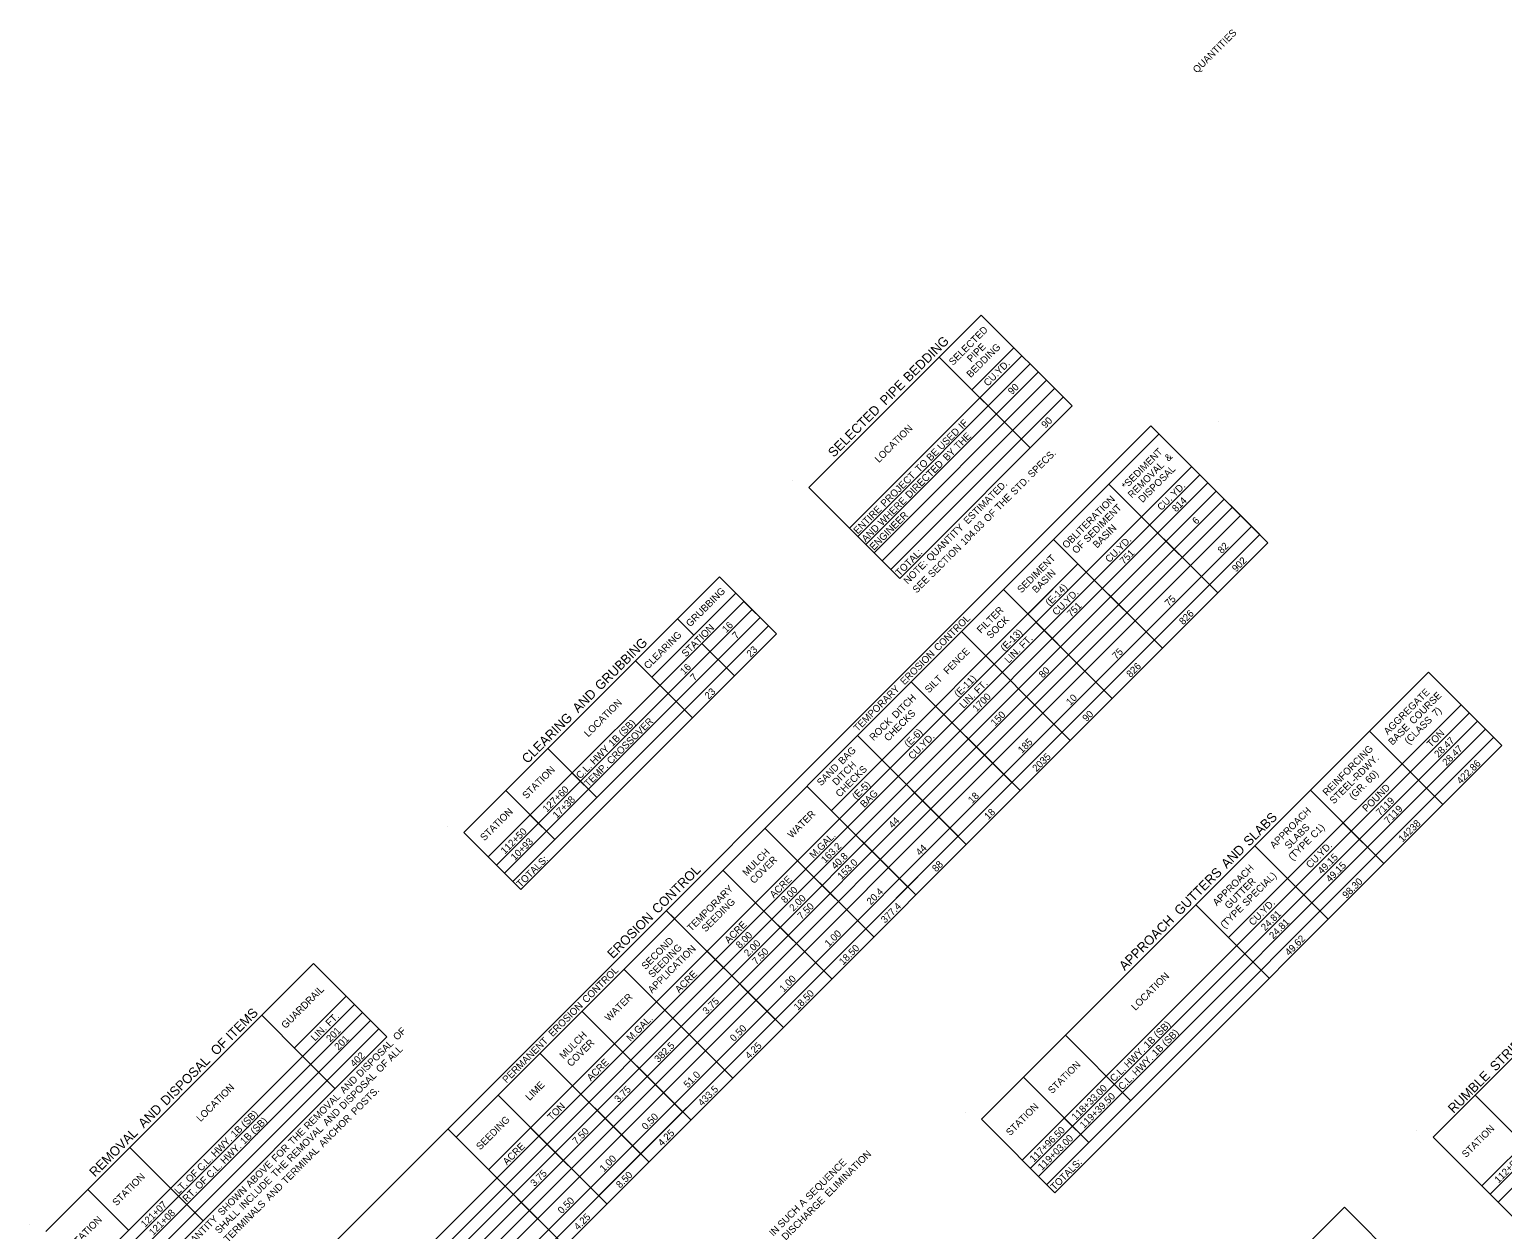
# Model space of a CAD drawing. Extents: x 1675667 to 1681231, y 227227 to 232694.
# Drawn here: x 1676937 to 1678183, y 229090 to 230105 of the extents above; entities that cross this region are included whole.
import ezdxf

# ---------------------------------------------------------------- set-up
doc = ezdxf.new("R2010")
doc.units = 0
for name, color, linetype in [('Default', 7, 'Continuous'), ('R_Annotation', 7, 'Continuous'), ('R_Border', 7, 'Continuous')]:
    doc.layers.add(name, color=color, linetype=linetype)

msp = doc.modelspace()

# ---------------------------------------------------------------- linework, layer by layer
at = {"layer": 'Default'}
for p, q in [((1677596.4, 229717.2), (1677742.2, 229863)), ((1677819.1, 229786.1), (1677742.2, 229863)), ((1677819.1, 229786.1), (1677742.2, 229863)), ((1677734.3, 229799.9), (1677769.8, 229835.4)), ((1677630.9, 229682.7), (1677776.7, 229828.5)), ((1677783.6, 229750.6), (1677706.7, 229827.5)), ((1677637.8, 229675.8), (1677783.6, 229821.7)), ((1677644.7, 229668.9), (1677790.5, 229814.8)), ((1677651.6, 229662), (1677797.4, 229807.9)), ((1677658.5, 229655.1), (1677804.3, 229801)), ((1677665.7, 229647.9), (1677811.5, 229793.7)), ((1677673.3, 229640.3), (1677819.1, 229786.1)), ((1677783.6, 229750.6), (1677741.2, 229793)), ((1677056.4, 228939.9), (1677885.7, 229769.4)), ((1677298.1, 229167.8), (1677892.6, 229762.5)), ((1677984.7, 229670.5), (1677885.7, 229769.4)), ((1677325.6, 229140.2), (1677920.2, 229734.9)), ((1677830.9, 229645.6), (1677920.2, 229734.9)), ((1677097.8, 228898.5), (1677927.1, 229728)), ((1677582.7, 229722.7), (1677582.7, 229722.7)), ((1677977.8, 229677.4), (1677927.1, 229728)), ((1677104.7, 228891.6), (1677934, 229721.1)), ((1677111.6, 228884.7), (1677940.9, 229714.2)), ((1677673.3, 229640.3), (1677596.4, 229717.2)), ((1677673.3, 229640.3), (1677596.4, 229717.2)), ((1677942.3, 229628.1), (1677850.2, 229720.1)), ((1677118.5, 228877.9), (1677947.8, 229707.3)), ((1677125.4, 228871), (1677954.7, 229700.4)), ((1677132.3, 228864.1), (1677961.6, 229693.6)), ((1677942.3, 229628.1), (1677877.8, 229692.5)), ((1677141.6, 228854.8), (1677970.9, 229684.2)), ((1677148.5, 228847.9), (1677977.8, 229677.4)), ((1677895.4, 229581.2), (1677803.3, 229673.2)), ((1677935.4, 229634.9), (1677977.8, 229677.4)), ((1677155.4, 228841), (1677984.7, 229670.5)), ((1677615.5, 229443.9), (1677824, 229652.5)), ((1677781.6, 229610.1), (1677824, 229652.5)), ((1677304.7, 229425.4), (1677520.8, 229641.5)), ((1677569.1, 229593.3), (1677520.8, 229641.5)), ((1677534.6, 229627.7), (1677520.8, 229641.5)), ((1677895.4, 229581.2), (1677830.9, 229645.6)), ((1677463.6, 229556.7), (1677534.6, 229627.7)), ((1677853, 229538.8), (1677761, 229630.8)), ((1677768.2, 229467.7), (1677935.4, 229634.9)), ((1677325.4, 229404.7), (1677541.5, 229620.8)), ((1677332.3, 229397.8), (1677548.4, 229614)), ((1677562.2, 229600.2), (1677541.5, 229620.8)), ((1677339.2, 229390.9), (1677555.3, 229607.1)), ((1677346.1, 229384), (1677562.2, 229600.2)), ((1677417.1, 229455), (1677562.2, 229600.2)), ((1677499.1, 229592.2), (1677485.3, 229606)), ((1677853, 229538.8), (1677788.5, 229603.2)), ((1677353, 229377.1), (1677569.1, 229593.3)), ((1677533.6, 229557.8), (1677506, 229585.3)), ((1677533.6, 229557.8), (1677506, 229585.3)), ((1677817.5, 229503.3), (1677725.5, 229595.3)), ((1677817.5, 229503.3), (1677725.5, 229595.3)), ((1677498.1, 229522.3), (1677449.8, 229570.5)), ((1677742.4, 229182.9), (1678120.5, 229561.1)), ((1678182.6, 229499), (1678120.5, 229561.1)), ((1677491.2, 229529.1), (1677463.6, 229556.7)), ((1677775.1, 229460.8), (1677683.1, 229552.9)), ((1677768.2, 229467.7), (1677710.6, 229525.3)), ((1677776.9, 229148.4), (1678155, 229526.6)), ((1677951.3, 229336.6), (1678148.1, 229533.5)), ((1678182.6, 229499), (1678148.1, 229533.5)), ((1677783.8, 229141.5), (1678161.9, 229519.7)), ((1677790.7, 229134.6), (1678168.8, 229512.8)), ((1678132.6, 229449), (1678070.5, 229511.1)), ((1677729.6, 229415.3), (1677637.6, 229507.4)), ((1677797.6, 229127.7), (1678175.7, 229505.9)), ((1677804.5, 229120.8), (1678182.6, 229499)), ((1677417.1, 229455), (1677375.7, 229496.4)), ((1677417.1, 229455), (1677396.4, 229475.7)), ((1677722.7, 229422.2), (1677665.1, 229479.8)), ((1678132.6, 229449), (1678098.1, 229483.5)), ((1677381.6, 229419.5), (1677340.2, 229460.9)), ((1677686.9, 229372.6), (1677594.8, 229464.6)), ((1677609, 229308.5), (1677768.2, 229467.7)), ((1678082.6, 229399.1), (1678020.6, 229461.1)), ((1677381.6, 229419.5), (1677360.9, 229440.2)), ((1677680, 229379.5), (1677622.4, 229437)), ((1677290.9, 229430.9), (1677290.9, 229430.9)), ((1677353, 229377.1), (1677304.7, 229425.4)), ((1677353, 229377.1), (1677304.7, 229425.4)), ((1677651.4, 229337.1), (1677559.3, 229429.1)), ((1678082.6, 229399.1), (1678048.1, 229433.5)), ((1678035.7, 229352.2), (1677973.7, 229414.2)), ((1677651.4, 229337.1), (1677586.9, 229401.5)), ((1677615.9, 229301.6), (1677523.8, 229393.6)), ((1678035.7, 229352.2), (1678001.3, 229386.6)), ((1677615.9, 229301.6), (1677551.4, 229366)), ((1677985.8, 229302.2), (1677923.7, 229364.2)), ((1678124.4, 229167.8), (1678325.3, 229368.8)), ((1677482.8, 229352.6), (1677475.9, 229359.5)), ((1677574.9, 229260.5), (1677475.9, 229359.5)), ((1677568, 229267.4), (1677510.4, 229325)), ((1677985.8, 229302.2), (1677958.2, 229329.8)), ((1678165.7, 229126.5), (1678366.7, 229327.5)), ((1676951.2, 229088.1), (1677177.6, 229314.6)), ((1677212.1, 229280.1), (1677177.6, 229314.6)), ((1677239.7, 229252.5), (1677177.6, 229314.6)), ((1678172.6, 229119.6), (1678373.6, 229320.6)), ((1678179.5, 229112.7), (1678380.5, 229313.7)), ((1677532.1, 229217.8), (1677440.1, 229309.8)), ((1677568, 229267.4), (1677609, 229308.5)), ((1677161.4, 229243.2), (1677205.2, 229287)), ((1676985.6, 229053.6), (1677212.1, 229280.1)), ((1676985.6, 229053.6), (1677212.1, 229280.1)), ((1677239.7, 229252.5), (1677212.1, 229280.1)), ((1677496.6, 229182.3), (1677404.6, 229274.3)), ((1677525.2, 229224.7), (1677467.6, 229282.2)), ((1676992.5, 229046.7), (1677219, 229273.2)), ((1676999.4, 229039.8), (1677225.9, 229266.3)), ((1677168.3, 229236.3), (1677133.8, 229270.8)), ((1677418.7, 229118.2), (1677568, 229267.4)), ((1677006.3, 229032.9), (1677232.8, 229259.4)), ((1677013.2, 229026), (1677239.7, 229252.5)), ((1677868.6, 229198.7), (1677813.4, 229253.9)), ((1677461.1, 229146.8), (1677369.1, 229238.8)), ((1677489.7, 229189.2), (1677432.1, 229246.7)), ((1677195.9, 229208.7), (1677168.3, 229236.3)), ((1677833.1, 229163.2), (1677777.9, 229218.4)), ((1677868.6, 229198.7), (1677847.9, 229219.4)), ((1677425.6, 229111.3), (1677333.6, 229203.3)), ((1677454.2, 229153.7), (1677396.6, 229211.2)), ((1678228.8, 229134.4), (1678159.9, 229203.3)), ((1678228.8, 229134.4), (1678159.9, 229203.3)), ((1677728.6, 229188.4), (1677728.6, 229188.4)), ((1677390.1, 229075.8), (1677291.2, 229174.7)), ((1677425.6, 229111.3), (1677361.1, 229175.7)), ((1677804.5, 229120.8), (1677742.4, 229182.9)), ((1677804.5, 229120.8), (1677742.4, 229182.9)), ((1677833.1, 229163.2), (1677812.4, 229183.9)), ((1678110.6, 229173.3), (1678110.6, 229173.3)), ((1678200.2, 229092), (1678124.4, 229167.8)), ((1678200.2, 229092), (1678124.4, 229167.8)), ((1677056.6, 229124.6), (1677022.2, 229159.1)), ((1677084.2, 229097), (1677056.6, 229124.6)), ((1677367, 229098.8), (1677332.5, 229133.3)), ((1677021.1, 229089.1), (1676986.7, 229123.6)), ((1677481.3, 228540.5), (1678049.3, 229108.6)), ((1678160, 228998), (1678049.3, 229108.6)), ((1676937.4, 229093.6), (1676937.4, 229093.6))]:
    msp.add_line(p, q, dxfattribs=at)
at = {"layer": 'R_Annotation'}
msp.add_line((1677942.7, 229772.9), (1677942.7, 229772.9), dxfattribs=at)

# ---------------------------------------------------------------- texts
at = {"layer": 'Default'}
for s, height, p in [('SELECTED', 6, (1677718.4, 229820)), (' BEDDING', 8, (1677679.1, 229803.8)), ('BEDDING', 6, (1677733.3, 229809.5)), ('PIPE', 6, (1677733.8, 229822.7)), ('CU.YD.', 6, (1677747.8, 229802.3)), (' PIPE', 8, (1677659.2, 229784)), ('90', 6, (1677768.3, 229795.2)), ('SELECTED', 8, (1677617.5, 229742.2)), (' IF', 6, (1677724.9, 229764.6)), ('90', 6, (1677796.6, 229766.9)), ('LOCATION', 6, (1677655.7, 229737.7)), (' USED', 6, (1677707.1, 229746.8)), (' THE', 6, (1677721.3, 229747.2)), (' BE', 6, (1677697.9, 229737.6)), (' BY', 6, (1677711.8, 229737.7)), (' SPECS.', 6, (1677783.6, 229723.4)), ('*SEDIMENT', 6, (1677864.6, 229715.3)), (' DIRECTED', 6, (1677680.1, 229706.1)), (' TO', 6, (1677688.3, 229728)), ('REMOVAL', 6, (1677869.7, 229707.7)), (' &', 6, (1677899.1, 229737.2)), (' PROJECT', 6, (1677659.1, 229698.8)), (' STD.', 6, (1677769, 229708.7)), ('DISPOSAL', 6, (1677878.6, 229703.9)), (' ESTIMATED.', 6, (1677729.2, 229684.1)), (' THE', 6, (1677755.8, 229695.6)), ('OBLITERATION', 6, (1677814.3, 229665.1)), (' YD.', 6, (1677904.4, 229707)), ('ENTIRE', 6, (1677637.7, 229677.4)), (' WHERE', 6, (1677656.8, 229682.7)), (' OF', 6, (1677746.2, 229685.9)), (' SEDIMENT', 6, (1677830.6, 229668.6)), ('CU.', 6, (1677894.6, 229697.2)), ('814', 6, (1677907.1, 229696)), ('AND', 6, (1677644.6, 229670.5)), ('ENGINEER', 6, (1677651.4, 229663.6)), (' QUANTITY', 6, (1677697.7, 229652.6)), (' 104.03', 6, (1677726.7, 229666.4)), ('BASIN', 6, (1677840.1, 229665.4)), ('6', 6, (1677924.2, 229685.5)), ('OF', 6, (1677822.6, 229660.7)), ('CU.YD.', 6, (1677850.6, 229653.2)), ('TOTAL:', 6, (1677673.2, 229641.9)), (' SECTION', 6, (1677699.2, 229638.9)), ('SEDIMENT', 6, (1677776.2, 229627.5)), ('751', 6, (1677862.9, 229651.7)), ('82', 6, (1677945.7, 229660.8)), ('NOTE:', 6, (1677680.1, 229635)), ('BASIN', 6, (1677788.8, 229627.4)), ('902', 6, (1677957.8, 229645.3)), ('SEE', 6, (1677687.6, 229627.4)), ('(E-14)', 6, (1677800, 229616.4)), ('GRUBBING', 6, (1677496.1, 229598.8)), ('CU.YD.', 6, (1677805.9, 229608.5)), ('75', 6, (1677901, 229616.1)), ('FILTER', 6, (1677742.1, 229593.4)), ('751', 6, (1677818.3, 229607.1)), ('826', 6, (1677913.1, 229600.6)), ('STATION', 6, (1677492.4, 229573.4)), ('16', 6, (1677526.6, 229593.9)), (' CONTROL', 6, (1677704.2, 229576.7)), ('SOCK', 6, (1677750.3, 229588.8)), (' GRUBBING', 8, (1677418.2, 229542.9)), ('CLEARING', 6, (1677460.5, 229563.1)), ('7', 6, (1677535.2, 229588.6)), ('(E-13)', 6, (1677761.9, 229578.2)), (' FT.', 6, (1677776.3, 229578.9)), ('23', 6, (1677547.3, 229573.2)), (' EROSION', 6, (1677675.7, 229548.2)), ('  FENCE', 6, (1677710.7, 229555.6)), ('LIN.', 6, (1677765.5, 229568.1)), ('75', 6, (1677856.4, 229571.4)), ('16', 6, (1677491.1, 229558.4)), ('80', 6, (1677794.4, 229555.6)), ('826', 6, (1677868.5, 229556)), ('7', 6, (1677499.7, 229553.1)), ('TEMPORARY', 6, (1677637.8, 229510.3)), ('SILT', 6, (1677698, 229542.9)), ('(E-11)', 6, (1677722.9, 229539.3)), (' FT.', 6, (1677738.2, 229540.8)), (' AND', 8, (1677399.3, 229524)), ('LOCATION', 6, (1677410, 229505.7)), ('23', 6, (1677511.8, 229537.7)), (' DITCH', 6, (1677668.7, 229519.9)), ('LIN.', 6, (1677727.4, 229530)), ('1700', 6, (1677738.3, 229527.1)), ('10', 6, (1677817.5, 229532.5)), ('AGGREGATE', 6, (1678086.1, 229507.6)), (' COURSE', 6, (1678106.2, 229514.9)), ('CLEARING', 8, (1677358.5, 229483.2)), ('CHECKS', 6, (1677663.6, 229502.1)), ('150', 6, (1677753.8, 229515)), ('90', 6, (1677831.3, 229518.7)), ('(CLASS', 6, (1678103.6, 229499.6)), (' 7)', 6, (1678125.4, 229521.4)), (' CROSSOVER', 6, (1677427.6, 229481.1)), (' (SB)', 6, (1677437.5, 229504.7)), ('ROCK', 6, (1677651.2, 229502.5)), ('(E-6)', 6, (1677680.6, 229497)), ('BASE', 6, (1678090, 229498.7)), ('TON', 6, (1678122.6, 229496.9)), (' HWY', 6, (1677413.5, 229480.7)), (' 1B', 6, (1677428.9, 229496.1)), ('CU.YD.', 6, (1677684.1, 229486.7)), ('185', 6, (1677776.8, 229491.9)), ('REINFORCING', 6, (1678034.5, 229456)), ('28.47', 6, (1678128.8, 229488.3)), ('28.47', 6, (1678135.7, 229481.4)), ('DITCH', 6, (1677619.8, 229464.7)), (' BAG', 6, (1677623.3, 229480.9)), ('2035', 6, (1677789, 229476.4)), ('STEEL-RDWY.', 6, (1678040.4, 229449.1)), ('422.86', 6, (1678147.8, 229465.9)), ('STATION', 6, (1677357.7, 229453.4)), ('C.L.', 6, (1677403.1, 229470.3)), ('TEMP.', 6, (1677410, 229463.5)), ('SAND', 6, (1677606.8, 229464.4)), ('CHECKS', 6, (1677622.6, 229454.8)), (' 60)', 6, (1678068.9, 229464.9)), ('127+60', 6, (1677374.9, 229442.1)), ('(E-5)', 6, (1677636.5, 229452.8)), ('BAG', 6, (1677643.4, 229446)), ('(GR.', 6, (1678056.8, 229452.8)), ('POUND', 6, (1678068.1, 229442.4)), ('17+38', 6, (1677383.4, 229436.8)), ('18', 6, (1677734.6, 229449.6)), ('7119', 6, (1678079.6, 229439.1)), ('7119', 6, (1678086.5, 229432.2)), ('STATION', 6, (1677322.1, 229417.9)), ('WATER', 6, (1677582.1, 229420.1)), ('44', 6, (1677667.4, 229428.5)), ('18', 6, (1677748.3, 229435.8)), (' SLABS', 8, (1677966.7, 229411.2)), ('APPROACH', 6, (1677989.9, 229411.4)), ('14238', 6, (1678098.6, 229416.8)), ('112+50', 6, (1677339.4, 229406.6)), ('SLABS', 6, (1678002.3, 229411)), (' C1)', 6, (1678022.5, 229418.5)), ('10+93', 6, (1677347.9, 229401.3)), ('MULCH', 6, (1677543.8, 229388.1)), ('M.GAL.', 6, (1677600.5, 229403.1)), ('163.2', 6, (1677610.3, 229399.1)), ('44', 6, (1677690.4, 229405.4)), (' AND', 8, (1677947.8, 229392.3)), ('(TYPE', 6, (1678005.4, 229401.4)), ('CU.YD.', 6, (1678020.4, 229394.7)), ('TOTALS:', 6, (1677352.8, 229378.6)), ('COVER', 6, (1677550.1, 229381.7)), ('40.8', 6, (1677618.9, 229393.8)), ('153.0', 6, (1677624.1, 229385.3)), ('88', 6, (1677704.2, 229391.6)), ('APPROACH', 6, (1677941.5, 229362.9)), ('49.15', 6, (1678030.3, 229389.8)), ('49.15', 6, (1678037.2, 229382.9)), (' CONTROL', 8, (1677466.5, 229354)), ('ACRE', 6, (1677566.9, 229369.5)), (' GUTTERS', 8, (1677908.2, 229352.7)), ('GUTTER', 6, (1677951.6, 229360.3)), (' SPECIAL)', 6, (1677965, 229361)), ('98.30', 6, (1678051.1, 229369.2)), ('TEMPORARY', 6, (1677497.1, 229341.4)), ('8.00', 6, (1677576.5, 229365.2)), ('20.4', 6, (1677648.9, 229363.8)), ('SEEDING', 6, (1677509.2, 229340.8)), ('2.00', 6, (1677583.4, 229358.3)), ('7.50', 6, (1677590.3, 229351.4)), ('377.4', 6, (1677660.9, 229348.3)), ('(TYPE', 6, (1677947.9, 229343.9)), ('CU.YD.', 6, (1677972, 229346.2)), ('EROSION', 8, (1677430.7, 229318.2)), ('ACRE', 6, (1677528.7, 229331.2)), ('APPROACH', 8, (1677863.6, 229308.1)), ('24.81', 6, (1677982.3, 229341.8)), ('24.81', 6, (1677989.2, 229334.9)), ('SECOND', 6, (1677458.4, 229309.1)), ('8.00', 6, (1677538.2, 229326.9)), ('1.00', 6, (1677613.4, 229328.3)), ('49.62', 6, (1678002.6, 229320.8)), ('SEEDING', 6, (1677464.2, 229302.1)), ('APPLICATION', 6, (1677463.9, 229289.1)), ('2.00', 6, (1677545.1, 229320.1)), ('7.50', 6, (1677552, 229313.2)), ('18.50', 6, (1677625.5, 229312.9)), (' CONTROL', 6, (1677406.7, 229279.1)), ('ACRE', 6, (1677486.8, 229289.3)), ('1.00', 6, (1677575.1, 229290.1)), ('LOCATION', 6, (1677872.7, 229274.5)), ('GUARDRAIL', 6, (1677153.9, 229259.1)), ('WATER', 6, (1677427.4, 229265.3)), ('18.50', 6, (1677587.2, 229274.6)), (' ITEMS', 8, (1677106.1, 229247)), (' EROSION', 6, (1677378.2, 229250.6)), ('3.75', 6, (1677510.1, 229271.2)), (' FT.', 6, (1677189.7, 229259.4)), ('M.GAL.', 6, (1677445.8, 229248.3)), ('0.50', 6, (1677533.2, 229248.2)), (' (SB)', 6, (1677890.1, 229249.6)), (' OF', 8, (1677093.3, 229234.2)), ('LIN.', 6, (1677178.9, 229248.6)), ('201', 6, (1677191.8, 229247.8)), ('201', 6, (1677198.7, 229240.9)), (' OF', 6, (1677246.8, 229247.6)), ('PERMANENT', 6, (1677340.8, 229213.1)), ('MULCH', 6, (1677389.1, 229233.4)), ('COVER', 6, (1677395.4, 229226.9)), (' 1B', 6, (1677881.6, 229241)), (' (SB)', 6, (1677897, 229242.7)), (' STRIPS', 8, (1678175.1, 229220.9)), ('402', 6, (1677212.1, 229226.7)), (' DISPOSAL', 6, (1677215.7, 229216.5)), (' ALL', 6, (1677241.9, 229229.9)), ('382.5', 6, (1677469.3, 229230.5)), ('4.25', 6, (1677546.1, 229233.5)), (' HWY.', 6, (1677865, 229224.4)), (' HWY.', 6, (1677871.9, 229217.5)), (' 1B', 6, (1677888.5, 229234.1)), (' DISPOSAL', 8, (1677050.9, 229191.8)), (' OF', 6, (1677232.3, 229220.3)), ('ACRE', 6, (1677412.2, 229214.7)), ('STATION', 6, (1677802.2, 229204)), ('C.L.', 6, (1677854.6, 229214.1)), ('RUMBLE', 8, (1678141.7, 229187.4)), ('LOCATION', 6, (1677082.1, 229180.3)), (' DISPOSAL', 6, (1677201.3, 229189.2)), (' AND', 6, (1677201.9, 229202.6)), ('LIME', 6, (1677360.3, 229198.2)), ('51.0', 6, (1677494.1, 229209)), ('433.5', 6, (1677506.2, 229193.6)), ('118+33.00', 6, (1677822.2, 229181.7)), ('C.L.', 6, (1677861.5, 229207.2)), (' REMOVAL', 6, (1677171.5, 229172.2)), (' POSTS.', 6, (1677211.4, 229184.5)), ('3.75', 6, (1677435.5, 229196.6)), ('119+39.50', 6, (1677829.1, 229174.8)), (' AND', 8, (1677032, 229172.9)), (' (SB)', 6, (1677118.2, 229174.1)), (' ANCHOR', 6, (1677184.1, 229157.3)), (' AND', 6, (1677187.4, 229175.3)), ('TON', 6, (1677378.9, 229181.4)), ('0.50', 6, (1677458.6, 229173.5)), ('STATION', 6, (1677766.7, 229168.5)), (' 1B', 6, (1677109.6, 229165.5)), (' (SB)', 6, (1677126.1, 229168.2)), (' REMOVAL', 6, (1677157, 229144.9)), (' THE', 6, (1677158.3, 229159)), ('SEEDING', 6, (1677318.6, 229156.5)), ('7.50', 6, (1677400, 229161.1)), ('4.25', 6, (1677472.3, 229159.7)), ('117+96.50', 6, (1677786.7, 229146.2)), ('STATION', 6, (1678152.2, 229150)), ('REMOVAL', 8, (1676992.7, 229133.6)), (' HWY.', 6, (1677093, 229148.9)), (' HWY.', 6, (1677100.9, 229143)), (' 1B', 6, (1677117.5, 229159.6)), (' FOR', 6, (1677144.2, 229144.9)), ('ACRE', 6, (1677341.2, 229143.7)), ('119+03.00', 6, (1677793.6, 229139.3)), (' C.L.', 6, (1677081, 229136.9)), (' TERMINAL', 6, (1677152.7, 229125.9)), ('1.00', 6, (1677423.1, 229138)), (' SEQUENCE', 6, (1677595.5, 229112.5)), (' ELIMINATION', 6, (1677611.9, 229115.2)), ('112+50', 6, (1678179.7, 229128.4)), ('STATION', 6, (1677011, 229109.2)), (' OF', 6, (1677071.4, 229127.3)), (' C.L.', 6, (1677088.9, 229131)), (' ABOVE', 6, (1677122.4, 229123.2)), (' THE', 6, (1677143.8, 229131.7)), ('3.75', 6, (1677364.5, 229125.6)), ('8.50', 6, (1677436.9, 229124.2)), ('TOTALS:', 6, (1677804.3, 229122.4)), ('LT.', 6, (1677063.4, 229119.2)), (' OF', 6, (1677079.3, 229121.4)), (' SHOWN', 6, (1677098.6, 229099.3)), (' INCLUDE', 6, (1677116.5, 229104.3)), (' AND', 6, (1677138.9, 229112)), ('121+07', 6, (1677035.1, 229091)), ('RT.', 6, (1677070.3, 229112.4)), (' TERMINALS', 6, (1677103.6, 229076.8)), ('0.50', 6, (1677387.6, 229102.5)), (' DISCHARGE', 6, (1677575.4, 229078.6)), (' A', 6, (1677589.8, 229106.9)), ('STATION', 6, (1676974.7, 229072.9)), ('121+08', 6, (1677042, 229084.1)), (' QUANTITY', 6, (1677067, 229067.7)), (' SHALL', 6, (1677096.2, 229084.1)), ('4.25', 6, (1677401.3, 229088.7)), (' SUCH', 6, (1677571.9, 229089)), (' IN', 6, (1677564.8, 229081.9))]:
    msp.add_text(s, height=height, rotation=45.007, dxfattribs=at).set_placement(p)
at = {"layer": 'R_Border'}
msp.add_text('QUANTITIES', height=6, rotation=45.007, dxfattribs=at).set_placement((1677924.7, 230067.1))

doc.saveas('drawing.dxf')
